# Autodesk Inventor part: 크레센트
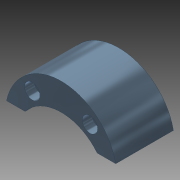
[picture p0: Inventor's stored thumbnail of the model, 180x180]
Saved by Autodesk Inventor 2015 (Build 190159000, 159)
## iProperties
Created: 2023-11
Part Number: 크레센트
Material: 강철, 합금
Document SubType Name: Modeling
Designer: mdu-01
Density: 1 g/cm^3
Appearance: 반광택(1)
Author: mdu-01
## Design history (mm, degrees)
sketch "스케치1"
  geometry: L1 (-28.373, 15)-(-18.735, 15); L2 (18.735, 15)-(28.373, 15); A1 r 24 centre (0, 0) between (-18.735, 15) and (18.735, 15); A2 r 29 centre (0, 9) between (-28.373, 15) and (28.373, 15); 1 further point
  constraints: 4 end point, 4 point on circle, 2 centre point, 2 horizontal, 1 coincident, 1 collinear, 1 vertical alignment
  dimensions: "d0" = 9 distance of A2.centre A1.centre; "d2" = 48 diameter of A1; "d3" = 58 diameter of A2; "d5" = 6 distance from line of L2 A2.centre
extrude "돌출1" new body sketch "스케치1" distance "d6" = 30; taper "d7" = 0 deg
sketch "스케치2"
  geometry: L1 (-15, 26)-(15, 26); L2 (18.735, 15)-(28.373, 15) reference; 2 further points
  constraints: 2 end point, 1 horizontal, 1 midpoint, 1 vertical alignment
  dimensions: "d8" = 11 distance between parallel lines of L1 L2; "d9" = 30 distance of L1.start L1.end
hole "구멍1" sketch "스케치2" at (15, 26), (-15, 26) diameter "d10" = 4.5; stored, may be unused: countersink angle "d14" = 90 deg, drill point angle "d16" = 118 deg; dims "d11" = 6, "d12" = 8, "d13" = 5, "d15" = 8
node "솔리드1"
other parameters: "d4" = 6
